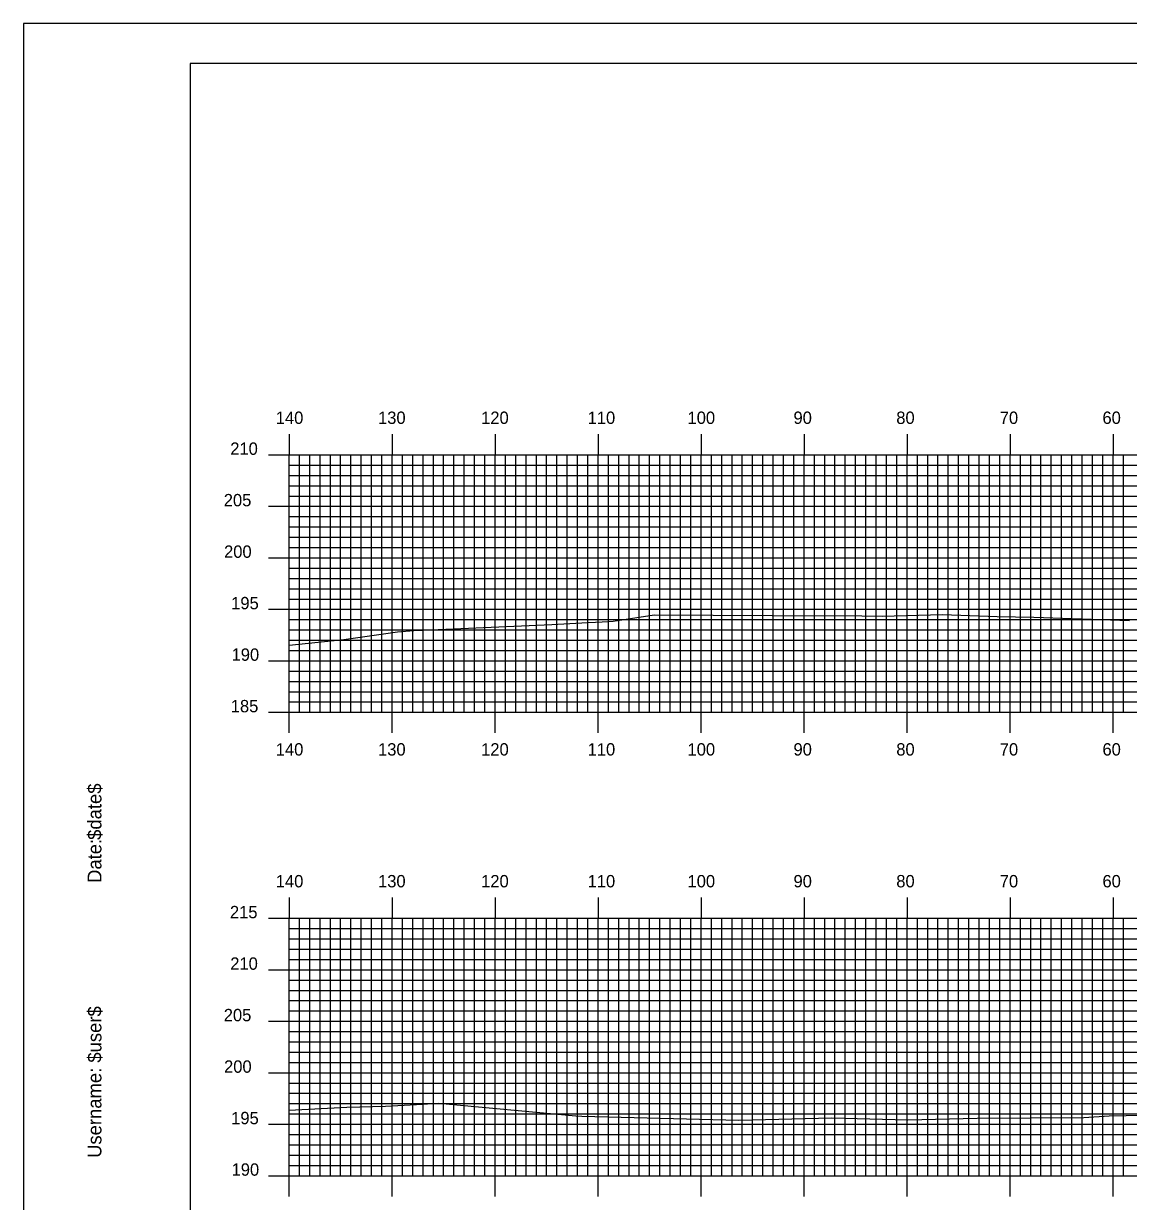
# Model space of a CAD drawing. Extents: x 1821998 to 1822342, y 442591 to 442811.
# Drawn here: x 1821998.5 to 1822105.8, y 442696.2 to 442810.5 of the extents above; entities that cross this region are included whole.
import ezdxf

# ---------------------------------------------------------------- set-up
doc = ezdxf.new("R2010")
doc.units = 0
for name, color, linetype in [('BORDER', 7, 'Continuous'), ('H_V ANNOTATION', 7, 'Continuous'), ('MAJOR', 7, 'Continuous'), ('MINOR', 7, 'Continuous'), ('PLOT BOUNDARY', 7, 'Continuous'), ('S_Roadway_Centerline', 7, 'Continuous')]:
    doc.layers.add(name, color=color, linetype=linetype)

msp = doc.modelspace()

# ---------------------------------------------------------------- linework, layer by layer
at = {"layer": 'BORDER'}
msp.add_lwpolyline([(1822014.66, 442596.67), (1822334.66, 442596.67), (1822334.66, 442806.67), (1822014.66, 442806.67)], close=True, dxfattribs=at)
at = {"layer": 'MAJOR'}
for p, q in [((1822024.26, 442770.67), (1822024.26, 442768.67)), ((1822034.26, 442770.67), (1822034.26, 442768.67)), ((1822044.26, 442770.67), (1822044.26, 442768.67)), ((1822054.26, 442770.67), (1822054.26, 442768.67)), ((1822064.26, 442770.67), (1822064.26, 442768.67)), ((1822074.26, 442770.67), (1822074.26, 442768.67)), ((1822084.26, 442770.67), (1822084.26, 442768.67)), ((1822094.26, 442770.67), (1822094.26, 442768.67)), ((1822104.26, 442770.67), (1822104.26, 442768.67)), ((1822022.25, 442768.67), (1822024.26, 442768.67)), ((1822024.26, 442768.67), (1822304.26, 442768.67)), ((1822024.26, 442743.67), (1822024.26, 442768.67)), ((1822024.26, 442743.67), (1822024.26, 442768.67)), ((1822024.26, 442768.67), (1822304.26, 442768.67)), ((1822034.26, 442743.67), (1822034.26, 442768.67)), ((1822044.26, 442743.67), (1822044.26, 442768.67)), ((1822054.26, 442743.67), (1822054.26, 442768.67)), ((1822064.26, 442743.67), (1822064.26, 442768.67)), ((1822074.26, 442743.67), (1822074.26, 442768.67)), ((1822084.26, 442743.67), (1822084.26, 442768.67)), ((1822094.26, 442743.67), (1822094.26, 442768.67)), ((1822104.26, 442743.67), (1822104.26, 442768.67)), ((1822022.25, 442763.67), (1822024.26, 442763.67)), ((1822024.26, 442763.67), (1822304.26, 442763.67)), ((1822022.25, 442758.67), (1822024.26, 442758.67)), ((1822024.26, 442758.67), (1822304.26, 442758.67)), ((1822022.25, 442753.67), (1822024.26, 442753.67)), ((1822024.26, 442753.67), (1822304.26, 442753.67)), ((1822022.25, 442748.67), (1822024.26, 442748.67)), ((1822024.26, 442748.67), (1822304.26, 442748.67)), ((1822022.25, 442743.67), (1822024.26, 442743.67)), ((1822024.26, 442743.67), (1822304.26, 442743.67)), ((1822024.26, 442743.67), (1822304.26, 442743.67)), ((1822024.26, 442741.66), (1822024.26, 442743.67)), ((1822034.26, 442741.66), (1822034.26, 442743.67)), ((1822044.26, 442741.66), (1822044.26, 442743.67)), ((1822054.26, 442741.66), (1822054.26, 442743.67)), ((1822064.26, 442741.66), (1822064.26, 442743.67)), ((1822074.26, 442741.66), (1822074.26, 442743.67)), ((1822084.26, 442741.66), (1822084.26, 442743.67)), ((1822094.26, 442741.66), (1822094.26, 442743.67)), ((1822104.26, 442741.66), (1822104.26, 442743.67)), ((1822024.26, 442725.67), (1822024.26, 442723.67)), ((1822034.26, 442725.67), (1822034.26, 442723.67)), ((1822044.26, 442725.67), (1822044.26, 442723.67)), ((1822054.26, 442725.67), (1822054.26, 442723.67)), ((1822064.26, 442725.67), (1822064.26, 442723.67)), ((1822074.26, 442725.67), (1822074.26, 442723.67)), ((1822084.26, 442725.67), (1822084.26, 442723.67)), ((1822094.26, 442725.67), (1822094.26, 442723.67)), ((1822104.26, 442725.67), (1822104.26, 442723.67)), ((1822022.25, 442723.67), (1822024.26, 442723.67)), ((1822024.26, 442723.67), (1822304.26, 442723.67)), ((1822024.26, 442698.67), (1822024.26, 442723.67)), ((1822024.26, 442698.67), (1822024.26, 442723.67)), ((1822024.26, 442723.67), (1822304.26, 442723.67)), ((1822034.26, 442698.67), (1822034.26, 442723.67)), ((1822044.26, 442698.67), (1822044.26, 442723.67)), ((1822054.26, 442698.67), (1822054.26, 442723.67)), ((1822064.26, 442698.67), (1822064.26, 442723.67)), ((1822074.26, 442698.67), (1822074.26, 442723.67)), ((1822084.26, 442698.67), (1822084.26, 442723.67)), ((1822094.26, 442698.67), (1822094.26, 442723.67)), ((1822104.26, 442698.67), (1822104.26, 442723.67)), ((1822022.25, 442718.67), (1822024.26, 442718.67)), ((1822024.26, 442718.67), (1822304.26, 442718.67)), ((1822022.25, 442713.67), (1822024.26, 442713.67)), ((1822024.26, 442713.67), (1822304.26, 442713.67)), ((1822022.25, 442708.67), (1822024.26, 442708.67)), ((1822024.26, 442708.67), (1822304.26, 442708.67)), ((1822022.25, 442703.67), (1822024.26, 442703.67)), ((1822024.26, 442703.67), (1822304.26, 442703.67)), ((1822022.25, 442698.67), (1822024.26, 442698.67)), ((1822024.26, 442698.67), (1822304.26, 442698.67)), ((1822024.26, 442698.67), (1822304.26, 442698.67)), ((1822024.26, 442696.66), (1822024.26, 442698.67)), ((1822034.26, 442696.66), (1822034.26, 442698.67)), ((1822044.26, 442696.66), (1822044.26, 442698.67)), ((1822054.26, 442696.66), (1822054.26, 442698.67)), ((1822064.26, 442696.66), (1822064.26, 442698.67)), ((1822074.26, 442696.66), (1822074.26, 442698.67)), ((1822084.26, 442696.66), (1822084.26, 442698.67)), ((1822094.26, 442696.66), (1822094.26, 442698.67)), ((1822104.26, 442696.66), (1822104.26, 442698.67))]:
    msp.add_line(p, q, dxfattribs=at)
at = {"layer": 'MINOR'}
for p, q in [((1822024.26, 442767.67), (1822304.26, 442767.67)), ((1822024.26, 442767.67), (1822026.26, 442767.67)), ((1822025.26, 442743.67), (1822025.26, 442768.67)), ((1822026.26, 442743.67), (1822026.26, 442768.67)), ((1822027.26, 442743.67), (1822027.26, 442768.67)), ((1822028.26, 442743.67), (1822028.26, 442768.67)), ((1822029.26, 442743.67), (1822029.26, 442768.67)), ((1822030.26, 442743.67), (1822030.26, 442768.67)), ((1822031.26, 442743.67), (1822031.26, 442768.67)), ((1822032.26, 442743.67), (1822032.26, 442768.67)), ((1822033.26, 442743.67), (1822033.26, 442768.67)), ((1822035.26, 442743.67), (1822035.26, 442768.67)), ((1822036.26, 442743.67), (1822036.26, 442768.67)), ((1822037.26, 442743.67), (1822037.26, 442768.67)), ((1822038.26, 442743.67), (1822038.26, 442768.67)), ((1822039.26, 442743.67), (1822039.26, 442768.67)), ((1822040.26, 442743.67), (1822040.26, 442768.67)), ((1822041.26, 442743.67), (1822041.26, 442768.67)), ((1822042.26, 442743.67), (1822042.26, 442768.67)), ((1822043.26, 442743.67), (1822043.26, 442768.67)), ((1822045.26, 442743.67), (1822045.26, 442768.67)), ((1822046.26, 442743.67), (1822046.26, 442768.67)), ((1822047.26, 442743.67), (1822047.26, 442768.67)), ((1822048.26, 442743.67), (1822048.26, 442768.67)), ((1822049.26, 442743.67), (1822049.26, 442768.67)), ((1822050.26, 442743.67), (1822050.26, 442768.67)), ((1822051.26, 442743.67), (1822051.26, 442768.67)), ((1822052.26, 442743.67), (1822052.26, 442768.67)), ((1822053.26, 442743.67), (1822053.26, 442768.67)), ((1822055.26, 442743.67), (1822055.26, 442768.67)), ((1822056.26, 442743.67), (1822056.26, 442768.67)), ((1822057.26, 442743.67), (1822057.26, 442768.67)), ((1822058.26, 442743.67), (1822058.26, 442768.67)), ((1822059.26, 442743.67), (1822059.26, 442768.67)), ((1822060.26, 442743.67), (1822060.26, 442768.67)), ((1822061.26, 442743.67), (1822061.26, 442768.67)), ((1822062.26, 442743.67), (1822062.26, 442768.67)), ((1822063.26, 442743.67), (1822063.26, 442768.67)), ((1822065.26, 442743.67), (1822065.26, 442768.67)), ((1822066.26, 442743.67), (1822066.26, 442768.67)), ((1822067.26, 442743.67), (1822067.26, 442768.67)), ((1822068.26, 442743.67), (1822068.26, 442768.67)), ((1822069.26, 442743.67), (1822069.26, 442768.67)), ((1822070.26, 442743.67), (1822070.26, 442768.67)), ((1822071.26, 442743.67), (1822071.26, 442768.67)), ((1822072.26, 442743.67), (1822072.26, 442768.67)), ((1822073.26, 442743.67), (1822073.26, 442768.67)), ((1822075.26, 442743.67), (1822075.26, 442768.67)), ((1822076.26, 442743.67), (1822076.26, 442768.67)), ((1822077.26, 442743.67), (1822077.26, 442768.67)), ((1822078.26, 442743.67), (1822078.26, 442768.67)), ((1822079.26, 442743.67), (1822079.26, 442768.67)), ((1822080.26, 442743.67), (1822080.26, 442768.67)), ((1822081.26, 442743.67), (1822081.26, 442768.67)), ((1822082.26, 442743.67), (1822082.26, 442768.67)), ((1822083.26, 442743.67), (1822083.26, 442768.67)), ((1822085.26, 442743.67), (1822085.26, 442768.67)), ((1822086.26, 442743.67), (1822086.26, 442768.67)), ((1822087.26, 442743.67), (1822087.26, 442768.67)), ((1822088.26, 442743.67), (1822088.26, 442768.67)), ((1822089.26, 442743.67), (1822089.26, 442768.67)), ((1822090.26, 442743.67), (1822090.26, 442768.67)), ((1822091.26, 442743.67), (1822091.26, 442768.67)), ((1822092.26, 442743.67), (1822092.26, 442768.67)), ((1822093.26, 442743.67), (1822093.26, 442768.67)), ((1822095.26, 442743.67), (1822095.26, 442768.67)), ((1822096.26, 442743.67), (1822096.26, 442768.67)), ((1822097.26, 442743.67), (1822097.26, 442768.67)), ((1822098.26, 442743.67), (1822098.26, 442768.67)), ((1822099.26, 442743.67), (1822099.26, 442768.67)), ((1822100.26, 442743.67), (1822100.26, 442768.67)), ((1822101.26, 442743.67), (1822101.26, 442768.67)), ((1822102.26, 442743.67), (1822102.26, 442768.67)), ((1822103.26, 442743.67), (1822103.26, 442768.67)), ((1822105.26, 442743.67), (1822105.26, 442768.67)), ((1822024.26, 442766.67), (1822304.26, 442766.67)), ((1822024.26, 442766.67), (1822026.26, 442766.67)), ((1822024.26, 442765.67), (1822304.26, 442765.67)), ((1822024.26, 442765.67), (1822026.26, 442765.67)), ((1822024.26, 442764.67), (1822304.26, 442764.67)), ((1822024.26, 442764.67), (1822026.26, 442764.67)), ((1822024.26, 442762.67), (1822304.26, 442762.67)), ((1822024.26, 442762.67), (1822026.26, 442762.67)), ((1822024.26, 442761.67), (1822304.26, 442761.67)), ((1822024.26, 442761.67), (1822026.26, 442761.67)), ((1822024.26, 442760.67), (1822304.26, 442760.67)), ((1822024.26, 442760.67), (1822026.26, 442760.67)), ((1822024.26, 442759.67), (1822304.26, 442759.67)), ((1822024.26, 442759.67), (1822026.26, 442759.67)), ((1822024.26, 442757.67), (1822304.26, 442757.67)), ((1822024.26, 442757.67), (1822026.26, 442757.67)), ((1822024.26, 442756.67), (1822304.26, 442756.67)), ((1822024.26, 442756.67), (1822026.26, 442756.67)), ((1822024.26, 442755.67), (1822304.26, 442755.67)), ((1822024.26, 442755.67), (1822026.26, 442755.67)), ((1822024.26, 442754.67), (1822304.26, 442754.67)), ((1822024.26, 442754.67), (1822026.26, 442754.67)), ((1822024.26, 442752.67), (1822304.26, 442752.67)), ((1822024.26, 442752.67), (1822026.26, 442752.67)), ((1822024.26, 442751.67), (1822304.26, 442751.67)), ((1822024.26, 442751.67), (1822026.26, 442751.67)), ((1822024.26, 442750.67), (1822304.26, 442750.67)), ((1822024.26, 442750.67), (1822026.26, 442750.67)), ((1822024.26, 442749.67), (1822304.26, 442749.67)), ((1822024.26, 442749.67), (1822026.26, 442749.67)), ((1822024.26, 442747.67), (1822304.26, 442747.67)), ((1822024.26, 442747.67), (1822026.26, 442747.67)), ((1822024.26, 442746.67), (1822304.26, 442746.67)), ((1822024.26, 442746.67), (1822026.26, 442746.67)), ((1822024.26, 442745.67), (1822304.26, 442745.67)), ((1822024.26, 442745.67), (1822026.26, 442745.67)), ((1822024.26, 442744.67), (1822304.26, 442744.67)), ((1822024.26, 442744.67), (1822026.26, 442744.67)), ((1822025.26, 442698.67), (1822025.26, 442723.67)), ((1822026.26, 442698.67), (1822026.26, 442723.67)), ((1822027.26, 442698.67), (1822027.26, 442723.67)), ((1822028.26, 442698.67), (1822028.26, 442723.67)), ((1822029.26, 442698.67), (1822029.26, 442723.67)), ((1822030.26, 442698.67), (1822030.26, 442723.67)), ((1822031.26, 442698.67), (1822031.26, 442723.67)), ((1822032.26, 442698.67), (1822032.26, 442723.67)), ((1822033.26, 442698.67), (1822033.26, 442723.67)), ((1822035.26, 442698.67), (1822035.26, 442723.67)), ((1822036.26, 442698.67), (1822036.26, 442723.67)), ((1822037.26, 442698.67), (1822037.26, 442723.67)), ((1822038.26, 442698.67), (1822038.26, 442723.67)), ((1822039.26, 442698.67), (1822039.26, 442723.67)), ((1822040.26, 442698.67), (1822040.26, 442723.67)), ((1822041.26, 442698.67), (1822041.26, 442723.67)), ((1822042.26, 442698.67), (1822042.26, 442723.67)), ((1822043.26, 442698.67), (1822043.26, 442723.67)), ((1822045.26, 442698.67), (1822045.26, 442723.67)), ((1822046.26, 442698.67), (1822046.26, 442723.67)), ((1822047.26, 442698.67), (1822047.26, 442723.67)), ((1822048.26, 442698.67), (1822048.26, 442723.67)), ((1822049.26, 442698.67), (1822049.26, 442723.67)), ((1822050.26, 442698.67), (1822050.26, 442723.67)), ((1822051.26, 442698.67), (1822051.26, 442723.67)), ((1822052.26, 442698.67), (1822052.26, 442723.67)), ((1822053.26, 442698.67), (1822053.26, 442723.67)), ((1822055.26, 442698.67), (1822055.26, 442723.67)), ((1822056.26, 442698.67), (1822056.26, 442723.67)), ((1822057.26, 442698.67), (1822057.26, 442723.67)), ((1822058.26, 442698.67), (1822058.26, 442723.67)), ((1822059.26, 442698.67), (1822059.26, 442723.67)), ((1822060.26, 442698.67), (1822060.26, 442723.67)), ((1822061.26, 442698.67), (1822061.26, 442723.67)), ((1822062.26, 442698.67), (1822062.26, 442723.67)), ((1822063.26, 442698.67), (1822063.26, 442723.67)), ((1822065.26, 442698.67), (1822065.26, 442723.67)), ((1822066.26, 442698.67), (1822066.26, 442723.67)), ((1822067.26, 442698.67), (1822067.26, 442723.67)), ((1822068.26, 442698.67), (1822068.26, 442723.67)), ((1822069.26, 442698.67), (1822069.26, 442723.67)), ((1822070.26, 442698.67), (1822070.26, 442723.67)), ((1822071.26, 442698.67), (1822071.26, 442723.67)), ((1822072.26, 442698.67), (1822072.26, 442723.67)), ((1822073.26, 442698.67), (1822073.26, 442723.67)), ((1822075.26, 442698.67), (1822075.26, 442723.67)), ((1822076.26, 442698.67), (1822076.26, 442723.67)), ((1822077.26, 442698.67), (1822077.26, 442723.67)), ((1822078.26, 442698.67), (1822078.26, 442723.67)), ((1822079.26, 442698.67), (1822079.26, 442723.67)), ((1822080.26, 442698.67), (1822080.26, 442723.67)), ((1822081.26, 442698.67), (1822081.26, 442723.67)), ((1822082.26, 442698.67), (1822082.26, 442723.67)), ((1822083.26, 442698.67), (1822083.26, 442723.67)), ((1822085.26, 442698.67), (1822085.26, 442723.67)), ((1822086.26, 442698.67), (1822086.26, 442723.67)), ((1822087.26, 442698.67), (1822087.26, 442723.67)), ((1822088.26, 442698.67), (1822088.26, 442723.67)), ((1822089.26, 442698.67), (1822089.26, 442723.67)), ((1822090.26, 442698.67), (1822090.26, 442723.67)), ((1822091.26, 442698.67), (1822091.26, 442723.67)), ((1822092.26, 442698.67), (1822092.26, 442723.67)), ((1822093.26, 442698.67), (1822093.26, 442723.67)), ((1822095.26, 442698.67), (1822095.26, 442723.67)), ((1822096.26, 442698.67), (1822096.26, 442723.67)), ((1822097.26, 442698.67), (1822097.26, 442723.67)), ((1822098.26, 442698.67), (1822098.26, 442723.67)), ((1822099.26, 442698.67), (1822099.26, 442723.67)), ((1822100.26, 442698.67), (1822100.26, 442723.67)), ((1822101.26, 442698.67), (1822101.26, 442723.67)), ((1822102.26, 442698.67), (1822102.26, 442723.67)), ((1822103.26, 442698.67), (1822103.26, 442723.67)), ((1822105.26, 442698.67), (1822105.26, 442723.67)), ((1822024.26, 442722.67), (1822304.26, 442722.67)), ((1822024.26, 442722.67), (1822026.26, 442722.67)), ((1822024.26, 442721.67), (1822304.26, 442721.67)), ((1822024.26, 442721.67), (1822026.26, 442721.67)), ((1822024.26, 442720.67), (1822304.26, 442720.67)), ((1822024.26, 442720.67), (1822026.26, 442720.67)), ((1822024.26, 442719.67), (1822304.26, 442719.67)), ((1822024.26, 442719.67), (1822026.26, 442719.67)), ((1822024.26, 442717.67), (1822304.26, 442717.67)), ((1822024.26, 442717.67), (1822026.26, 442717.67)), ((1822024.26, 442716.67), (1822304.26, 442716.67)), ((1822024.26, 442716.67), (1822026.26, 442716.67)), ((1822024.26, 442715.67), (1822304.26, 442715.67)), ((1822024.26, 442715.67), (1822026.26, 442715.67)), ((1822024.26, 442714.67), (1822304.26, 442714.67)), ((1822024.26, 442714.67), (1822026.26, 442714.67)), ((1822024.26, 442712.67), (1822304.26, 442712.67)), ((1822024.26, 442712.67), (1822026.26, 442712.67)), ((1822024.26, 442711.67), (1822304.26, 442711.67)), ((1822024.26, 442711.67), (1822026.26, 442711.67)), ((1822024.26, 442710.67), (1822304.26, 442710.67)), ((1822024.26, 442710.67), (1822026.26, 442710.67)), ((1822024.26, 442709.67), (1822304.26, 442709.67)), ((1822024.26, 442709.67), (1822026.26, 442709.67)), ((1822024.26, 442707.67), (1822304.26, 442707.67)), ((1822024.26, 442707.67), (1822026.26, 442707.67)), ((1822024.26, 442706.67), (1822304.26, 442706.67)), ((1822024.26, 442706.67), (1822026.26, 442706.67)), ((1822024.26, 442705.67), (1822304.26, 442705.67)), ((1822024.26, 442705.67), (1822026.26, 442705.67)), ((1822024.26, 442704.67), (1822304.26, 442704.67)), ((1822024.26, 442704.67), (1822026.26, 442704.67)), ((1822024.26, 442702.67), (1822304.26, 442702.67)), ((1822024.26, 442702.67), (1822026.26, 442702.67)), ((1822024.26, 442701.67), (1822304.26, 442701.67)), ((1822024.26, 442701.67), (1822026.26, 442701.67)), ((1822024.26, 442700.67), (1822304.26, 442700.67)), ((1822024.26, 442700.67), (1822026.26, 442700.67)), ((1822024.26, 442699.67), (1822304.26, 442699.67)), ((1822024.26, 442699.67), (1822026.26, 442699.67))]:
    msp.add_line(p, q, dxfattribs=at)
at = {"layer": 'PLOT BOUNDARY'}
msp.add_lwpolyline([(1821998.47, 442590.55), (1822338.47, 442590.55), (1822338.47, 442810.55), (1821998.47, 442810.55)], close=True, dxfattribs=at)
at = {"layer": 'S_Roadway_Centerline'}
for points in [[(1822024.26, 442750.2), (1822029.58, 442750.75), (1822034.77, 442751.48), (1822036.36, 442751.6), (1822037.99, 442751.69), (1822049.77, 442752.2), (1822053.26, 442752.4), (1822054.01, 442752.42), (1822055.3, 442752.47), (1822055.73, 442752.52), (1822059.71, 442753.14), (1822071.16, 442753.08), (1822079.87, 442753.04), (1822081.84, 442753), (1822087.7, 442753.16), (1822093.01, 442752.97), (1822096.56, 442752.9), (1822105.84, 442752.59)], [(1822024.26, 442705.04), (1822029.86, 442705.33), (1822033.61, 442705.41), (1822036.61, 442705.6), (1822038.79, 442705.7), (1822052.09, 442704.48), (1822052.68, 442704.45), (1822067.93, 442704.07), (1822076.94, 442704.29), (1822084.34, 442704.1), (1822091.07, 442704.27), (1822101.41, 442704.32), (1822103.88, 442704.49), (1822115.53, 442704.7)]]:
    msp.add_lwpolyline(points, dxfattribs=at)

# ---------------------------------------------------------------- texts
at = {"layer": 'BORDER'}
for s, p in [('$date$', (1822006.03, 442731.28)), ('Date:', (1822006.03, 442727.1)), ('$user$', (1822006.03, 442709.65)), ('Username:', (1822006.03, 442700.4))]:
    msp.add_text(s, height=1.339, rotation=90, dxfattribs=at).set_placement(p)
at = {"layer": 'H_V ANNOTATION'}
for s, p in [('140', (1822022.96, 442771.67)), ('130', (1822032.89, 442771.67)), ('120', (1822042.9, 442771.67)), ('110', (1822053.24, 442771.67)), ('100', (1822062.94, 442771.67)), ('90', (1822073.23, 442771.67)), ('80', (1822083.21, 442771.67)), ('70', (1822093.26, 442771.67)), ('60', (1822103.23, 442771.67)), ('210', (1822018.54, 442768.67)), ('205', (1822017.91, 442763.67)), ('200', (1822017.94, 442758.67)), ('195', (1822018.63, 442753.67)), ('190', (1822018.67, 442748.67)), ('185', (1822018.59, 442743.67)), ('140', (1822022.96, 442739.47)), ('130', (1822032.89, 442739.47)), ('120', (1822042.9, 442739.47)), ('110', (1822053.24, 442739.47)), ('100', (1822062.94, 442739.47)), ('90', (1822073.23, 442739.47)), ('80', (1822083.21, 442739.47)), ('70', (1822093.26, 442739.47)), ('60', (1822103.23, 442739.47)), ('140', (1822022.96, 442726.67)), ('130', (1822032.89, 442726.67)), ('120', (1822042.9, 442726.67)), ('110', (1822053.24, 442726.67)), ('100', (1822062.94, 442726.67)), ('90', (1822073.23, 442726.67)), ('80', (1822083.21, 442726.67)), ('70', (1822093.26, 442726.67)), ('60', (1822103.23, 442726.67)), ('215', (1822018.51, 442723.67)), ('210', (1822018.54, 442718.67)), ('205', (1822017.91, 442713.67)), ('200', (1822017.94, 442708.67)), ('195', (1822018.63, 442703.67)), ('190', (1822018.67, 442698.67))]:
    msp.add_text(s, height=1.2, dxfattribs=at).set_placement(p)
at = {"layer": 'MAJOR'}
for p in [(1822024.25, 442743.67), (1822024.25, 442698.67)]:
    msp.add_text('-', height=0.012, dxfattribs=at).set_placement(p)

doc.saveas('drawing.dxf')
